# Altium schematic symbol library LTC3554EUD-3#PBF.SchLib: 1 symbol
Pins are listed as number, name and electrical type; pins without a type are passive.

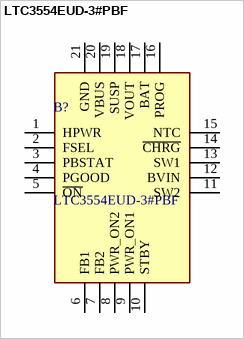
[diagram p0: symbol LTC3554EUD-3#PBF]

## LTC3554EUD-3#PBF
designator B?
Battery Management Micropower USB Power Manager with Li-Ion Charger and Two Step Down Regulators; Manufacturer_Name: Analog Devices; Geometry.Height: 0.8mm
footprint QFN40P300X300X80-21N-D
pins: 1 HPWR, 2 FSEL, 3 PBSTAT, 4 PGOOD, 5 ~{ON}, 6 FB1, 7 FB2, 8 PWR_ON2, 9 PWR_ON1, 10 STBY, 11 SW2, 12 BVIN, 13 SW1, 14 ~{CHRG}, 15 NTC, 16 PROG, 17 BAT, 18 VOUT, 19 SUSP, 20 VBUS, 21 GND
